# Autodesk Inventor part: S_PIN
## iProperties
Author: GJOHNST2
Shininess: 20.0
Length Units: 11272
Angle Units: 11286
Time Units: 11279
Mass Units: 11290
Length Display Precision: 3
Angle Display Precision: 2
Compacted: True
PropertySet Name: _Private Model Information
Created: 2001-11
Part Number: S_PIN
Document SubType Name: Modeling
Designer: GJOHNST2
Control State: 0
Master: False
Checked Out: False
PropertySet Name: Design Tracking Control
Density: 0.0
Volumn: 0.0
Area: 0.0
PropertySet Name: Model Information
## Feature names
1. Extrusion1
2. Extrusion2
3. Fillet1
4. Extrusion3
5. Fillet2
